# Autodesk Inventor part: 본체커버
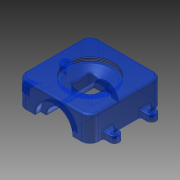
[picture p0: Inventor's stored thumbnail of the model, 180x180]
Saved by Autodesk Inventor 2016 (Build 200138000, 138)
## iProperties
Created: 2018-01
Part Number: 본체커버
Material: 알루미늄 6061
Document SubType Name: Modeling
Designer: mduedu
Density: 1 g/cm^3
Appearance: 선명 - 파란색
Author: mduedu
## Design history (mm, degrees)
sketch "스케치1"
  geometry: L1 (55, 55)-(-55, 55); L2 (-55, 55)-(-55, -55); L3 (-55, -55)-(55, -55); L4 (55, -55)-(55, 55); L5 (55, 55)-(-55, -55); L6 (-55, 55)-(55, -55); 1 further point
  constraints: 12 end point, 2 midpoint, 2 parallel, 1 horizontal, 1 perpendicular
  dimensions: "d0" = 110 distance of L3.end L2.end; "d1" = 110 distance of L2.end L1.end
extrude "돌출1" new body sketch "스케치1" distance "d2" = 38; taper "d3" = 0 deg
revolve "회전1" stored, may be unused: angle "d13" = 90 deg
fillet "모깎기1" dims "d14" = 1
fillet "모깎기2" dims "d15" = 13
fillet "모깎기3" dims "d16" = 3
sketch "스케치3"
  geometry: L1 (-15, -15)-(15, -15); L2 (15, -15)-(15, 15); L3 (15, 15)-(-15, 15); L4 (-15, 15)-(-15, -15); L5 (42, 55)-(-42, 55) reference; L6 (-15, -15)-(15, 15); L7 (15, -15)-(-15, 15); 2 further points
  constraints: 12 end point, 2 parallel, 1 horizontal, 1 midpoint, 1 perpendicular, 1 vertical alignment
  dimensions: "d19" = 30 distance of L3.end L1.start; "d20" = 30 distance between parallel lines of L2 L4; "d65" = 40 distance between parallel lines of L5 L3
extrude "돌출2" cut sketch "스케치3" stored distance "d21" = 38; taper "d22" = 0 deg
fillet "모깎기4" dims "d23" = 3
sketch "스케치4"
  geometry: L1 (38, 35)-(32, 35); L2 (32, 35)-(32, 31); L3 (32, 31)-(25, 15); L4 (25, 15)-(25, 0); L5 (25, 0)-(38, 0); L6 (38, 0)-(38, 35); L7 (38, 42)-(38, -42) reference; 1 further point
  constraints: 12 end point, 2 parallel, 1 collinear, 1 horizontal, 1 horizontal alignment, 1 perpendicular
  dimensions: "d24" = 6 distance of L1.start L1.end; "d26" = 70 diameter of L1 L5; "d28" = 62 diameter of L2.end L5; "d29" = 30 diameter of L3.end L5; "d30" = 7 horizontal distance of L2.end L3.end
revolve "회전2" sketch "스케치4" stored, may be unused: angle "d31" = 90 deg
feature "스레드1" dims "d74" = 10, "d75" = 0
chamfer "모따기2" distance "d36" = 1; stored, may be unused: second distance "d37" = 2, angle "d38" = 45 deg
sketch "스케치5"
  geometry: L1 (-42, 55)-(-29, 55) reference; L2 (-55, -42)-(-55, 42) reference; L3 (42, -55)-(-42, -55) reference; L4 (55, 42)-(55, -42) reference; L5 (55, 35)-(65, 35); L6 (65, 21)-(55, 21); L7 (55, 21)-(55, 35); L8 (55, 42)-(55, -42) reference; L9 (28, 54)-(28, 47) reference; L10 (28, 47)-(20, 47) reference; L11 (19, 46)-(19, -24) reference; L12 (18, -25)-(7.5, -25) reference; L13 (7.5, -25)-(5.479, -28.5) reference; L14 (4.613, -29)-(-4.613, -29) reference; L15 (-5.479, -28.5)-(-7.5, -25) reference; L16 (-7.5, -25)-(-18, -25) reference; L17 (-19, -24)-(-19, 46) reference; L18 (-20, 47)-(-28, 47) reference; L19 (-28, 47)-(-28, 54) reference; L20 (19, 46)-(20, 47) reference; L21 (-20, 47)-(-19, 46) reference; L22 (-29, 55)-(-28, 54) reference; L23 (29, 55)-(42, 55) reference; L24 (28, 54)-(29, 55) reference; A1 r 13 centre (-42, 42) between (-42, 55) and (-55, 42) reference; A2 r 13 centre (-42, -42) between (-55, -42) and (-42, -55) reference; A3 r 13 centre (42, -42) between (42, -55) and (55, -42) reference; A4 r 13 centre (42, 42) between (55, 42) and (42, 55) reference; A5 r 7 centre (65, 28) between (65, 21) and (65, 35); A6 r 1 centre (18, -24) between (18, -25) and (19, -24) reference; A7 r 1 centre (4.613, -28) between (4.613, -29) and (5.479, -28.5) reference; A8 r 1 centre (-4.613, -28) between (-5.479, -28.5) and (-4.613, -29) reference; A9 r 1 centre (-18, -24) between (-19, -24) and (-18, -25) reference; 1 further point
  constraints: 6 end point, 2 point on circle, 2 tangent, 1 centre point, 1 collinear, 1 horizontal, 1 parallel, 1 point on line
  dimensions: "d39" = 14 distance between parallel lines of L6 L5; "d41" = 28 vertical distance of A5.centre point (0, 0); "d42" = 10 distance from line of A5.centre L4
extrude "돌출3" join sketch "스케치5" distance "d43" = 10; taper "d44" = 0 deg
fillet "모깎기6" dims "d45" = 1
fillet "모깎기7" dims "d46" = 3
sketch "스케치6"
  geometry: A1 r 7 centre (-65, 28) between (-65, 35) and (-65, 21) reference; A2 r 7 centre (-65, -28) between (-65, -21) and (-65, -35) reference; A3 r 7 centre (65, -28) between (65, -35) and (65, -21) reference; A4 r 7 centre (65, 28) between (65, 21) and (65, 35) reference; 5 further points
  constraints: 4 coincident
sketch "스케치7"
  geometry: 4 further points
  constraints: 4 other
hole "구멍1" sketch "스케치7" at (-65, 28), (65, 28), (-65, -28), (65, -28) diameter "d47" = 4.5; stored, may be unused: countersink angle "d51" = 90 deg, drill point angle "d53" = 0 deg; dims "d48" = 6, "d49" = 8, "d50" = 4.6, "d52" = 8
sketch "스케치9" dims "d66" = 46
  geometry: 3 further points
  constraints: 2 vertical alignment, 1 coincident, 2 other
hole "구멍2" sketch "스케치9" at (0, 23) diameter "d67" = 3.242; stored, may be unused: countersink angle "d71" = 90 deg, drill point angle "d73" = 118 deg; dims "d68" = 9, "d69" = 4, "d70" = 2, "d72" = 11
sketch "스케치8"
  geometry: L1 (-97, 35)-(-97, 0) reference; L2 (0, 38)-(-84, 38) reference; 2 further points
  constraints: 1 other
  dimensions: "d54" = 55 distance from line of point (-42, 23) L1; "d55" = 15 distance from line of point (-42, 23) L2
feature "엠보싱1" sketch "스케치8" dims "d0" = 110, "d1" = 110, "d56" = 0.5, "d57" = 0
node "솔리드1"
mirror "대칭1"
mirror "대칭2"
sketch "스케치2"
  geometry: L1 (-55, 55)-(55, 55) reference; L2 (-55, -55)-(-55, 55) reference; L3 (55, -55)-(-55, -55) reference; L4 (55, 55)-(55, -55) reference; L5 (0, 55)-(28, 55); L6 (19, 47)-(19, -25); L7 (19, -25)-(7.5, -25); L8 (0, -25.854)-(0, 55); L9 (7.5, -25)-(5.191, -29); L10 (5.191, -29)-(0, -29); L11 (0, -29)-(0, -25.854); L12 (19, 47)-(28, 47); L13 (28, 47)-(28, 55); 1 further point
  constraints: 18 end point, 2 horizontal, 2 perpendicular, 1 midpoint, 1 parallel, 1 point on line, 1 vertical
  dimensions: "d7" = 38 diameter of L6 L8; "d58" = 4 distance between parallel lines of L7 L10; "d59" = 30 deg angle of L8 L9; "d60" = 15 diameter of L7.end L8; "d61" = 56 diameter of L13 L8; "d62" = 8 distance of L12.end L5.end; "d63" = 84 distance between parallel lines of L10 L5
node "투영된 루프1"
node "투영된 루프2"
